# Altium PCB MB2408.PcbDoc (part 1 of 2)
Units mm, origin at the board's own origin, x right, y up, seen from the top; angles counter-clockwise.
Board outline 43 x 47 mm, 2 copper layers (Top Layer, Bottom Layer), stack 0.996 mm thick; 66 components, 54 nets, 306 pads, 690 vias.
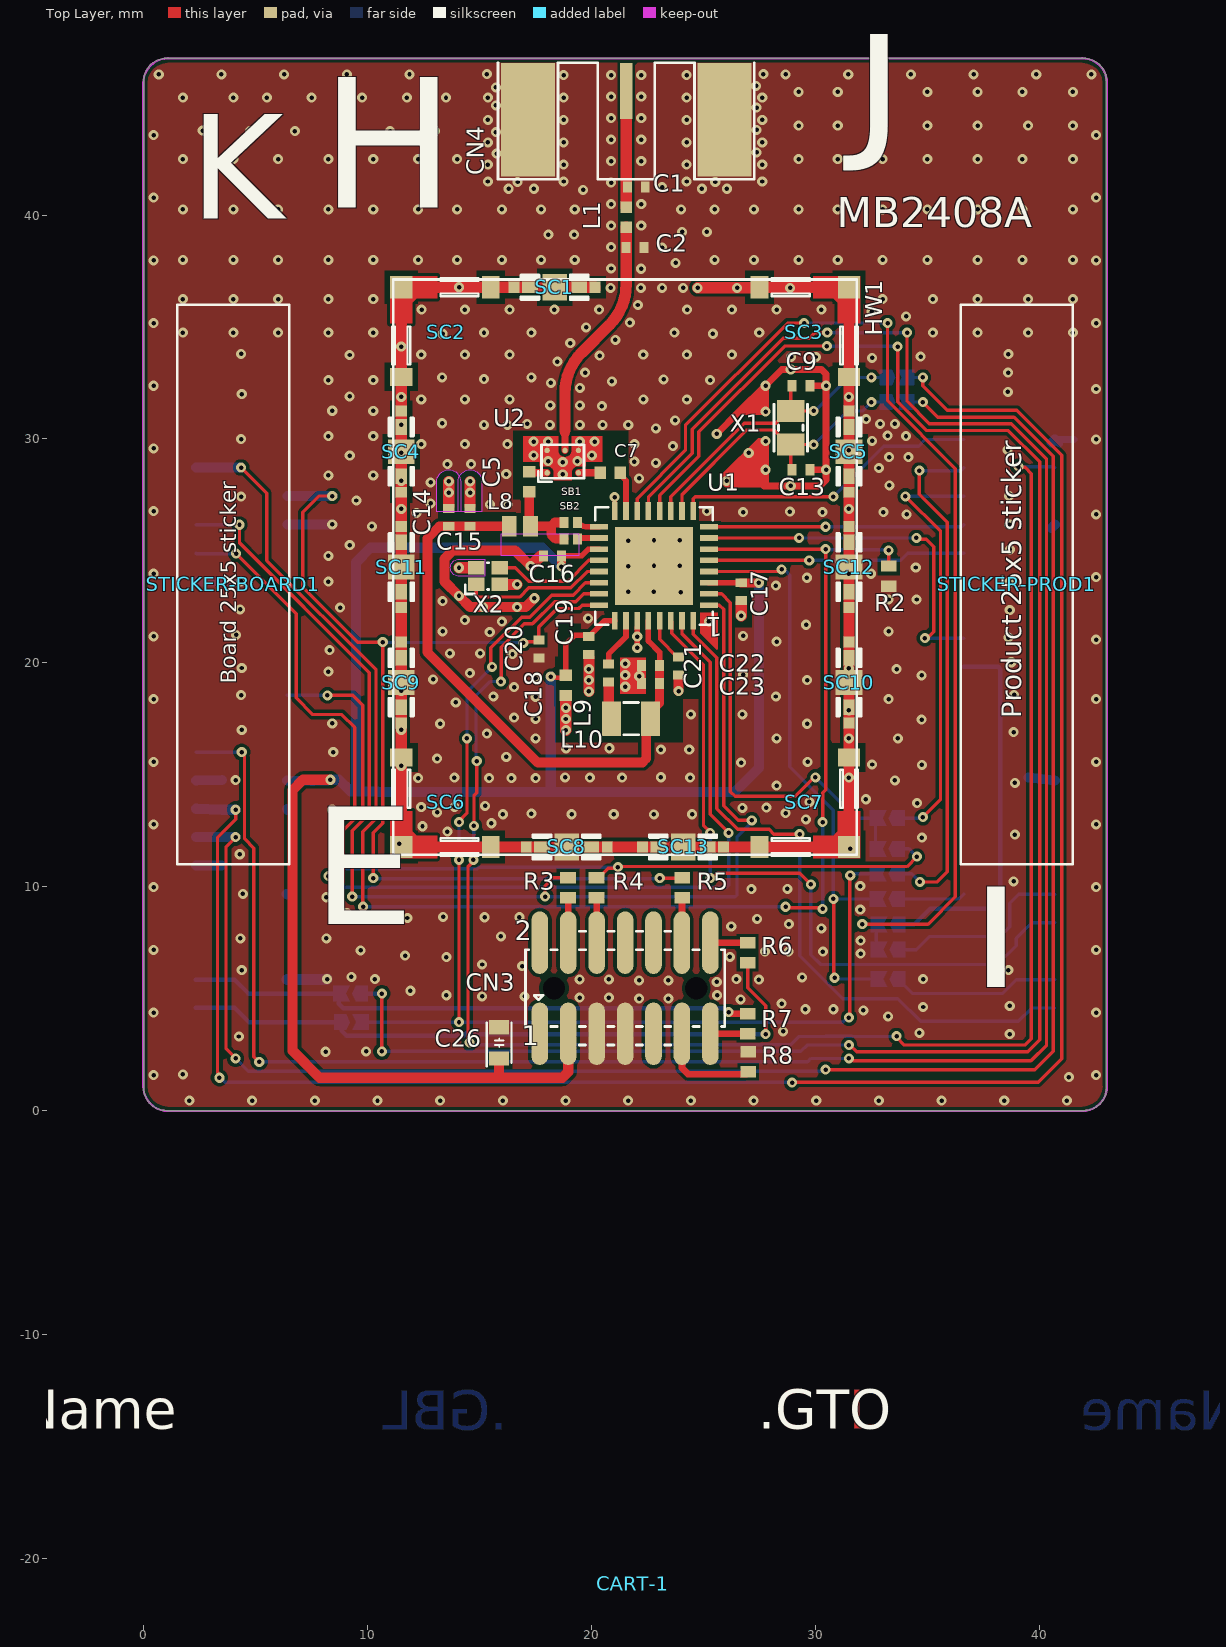
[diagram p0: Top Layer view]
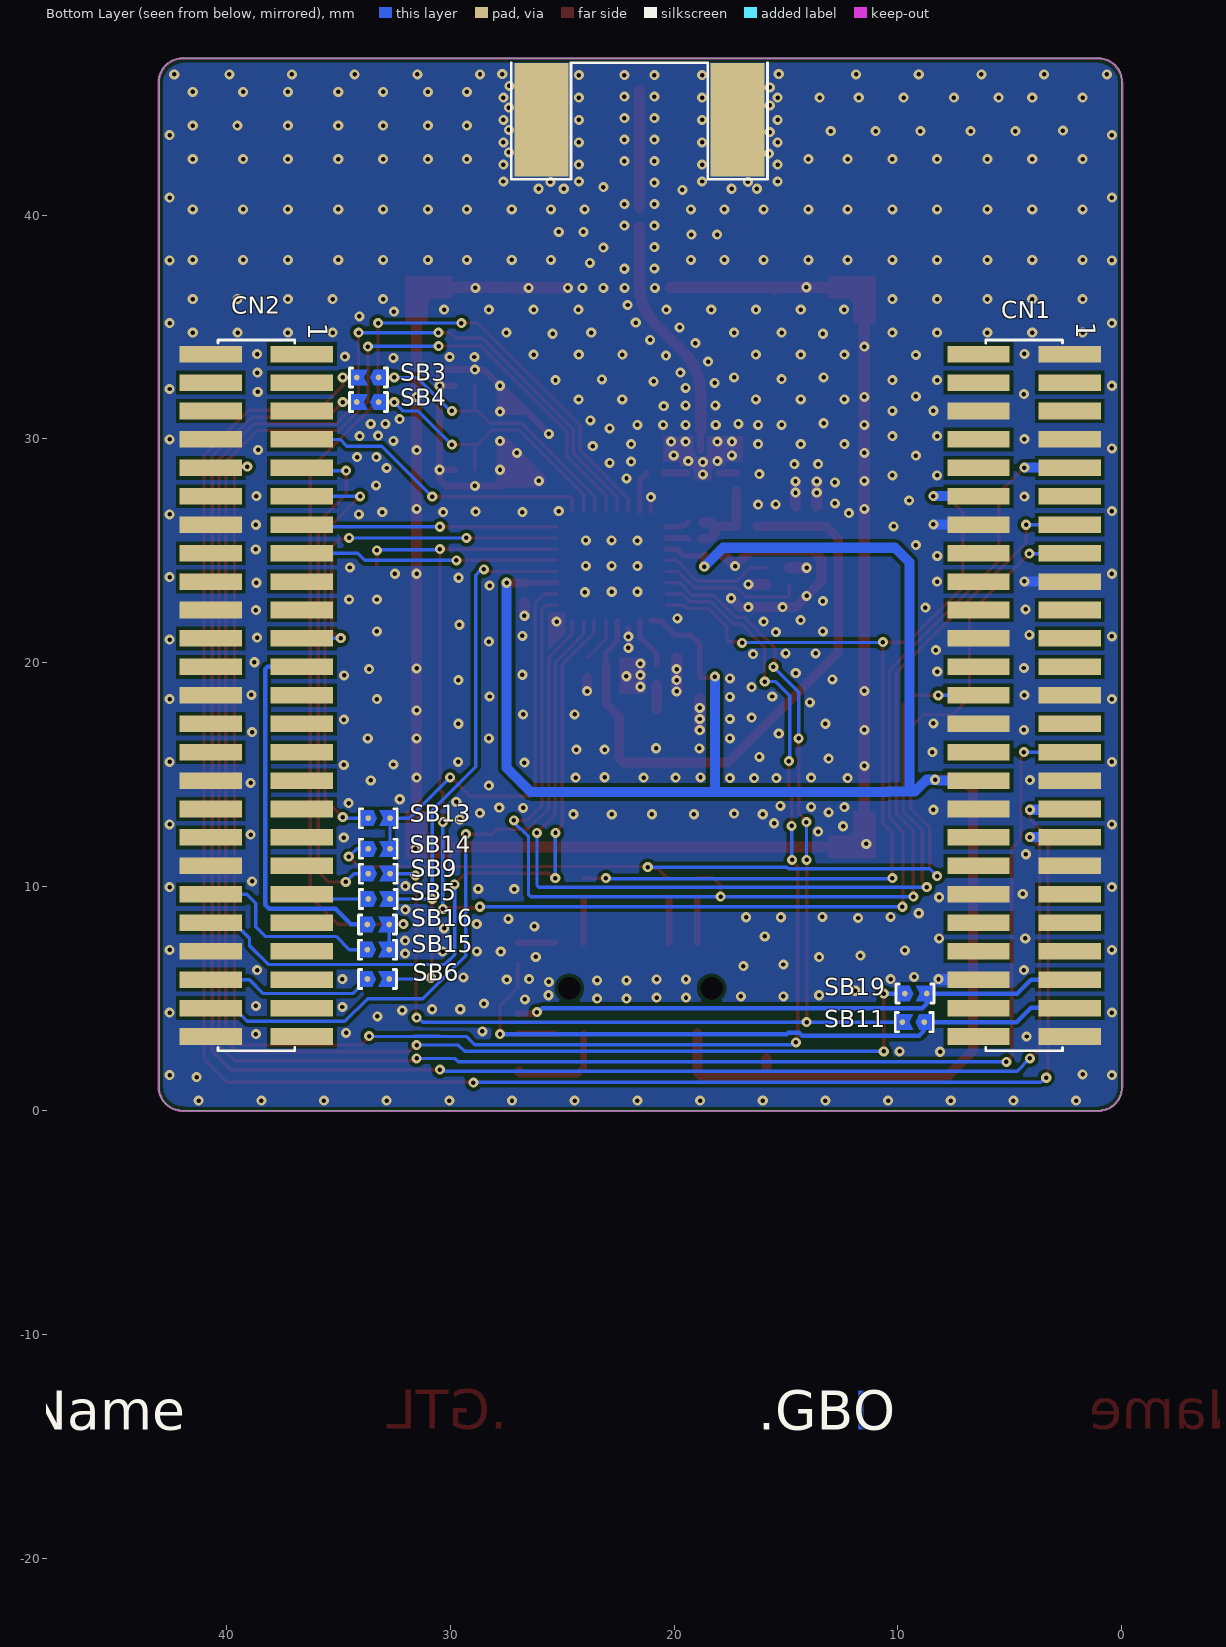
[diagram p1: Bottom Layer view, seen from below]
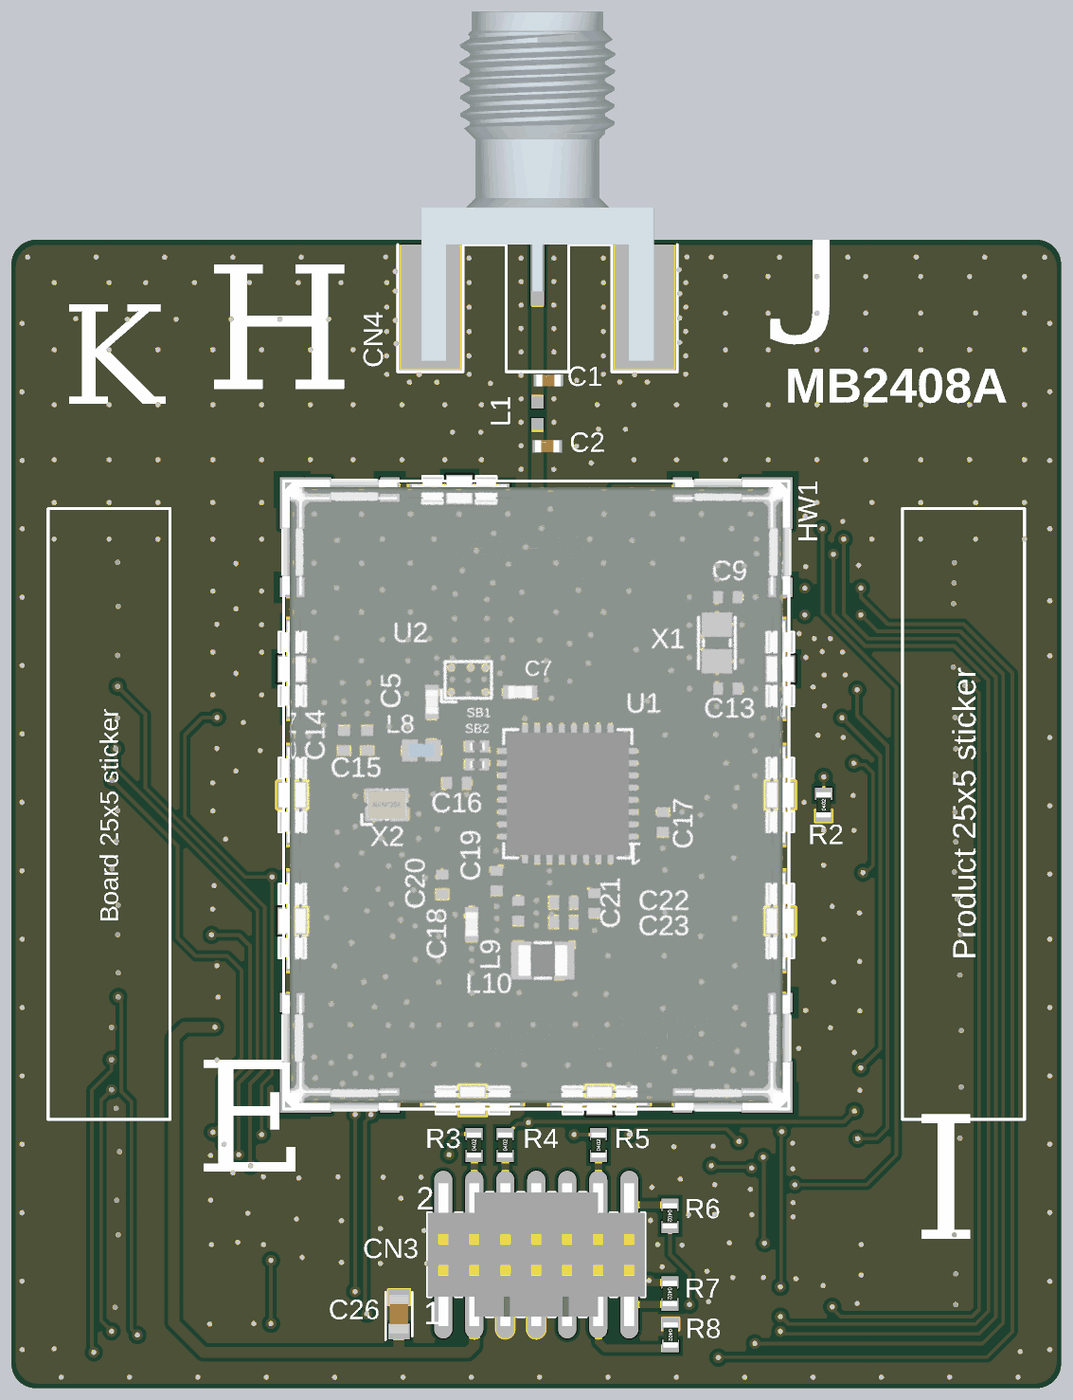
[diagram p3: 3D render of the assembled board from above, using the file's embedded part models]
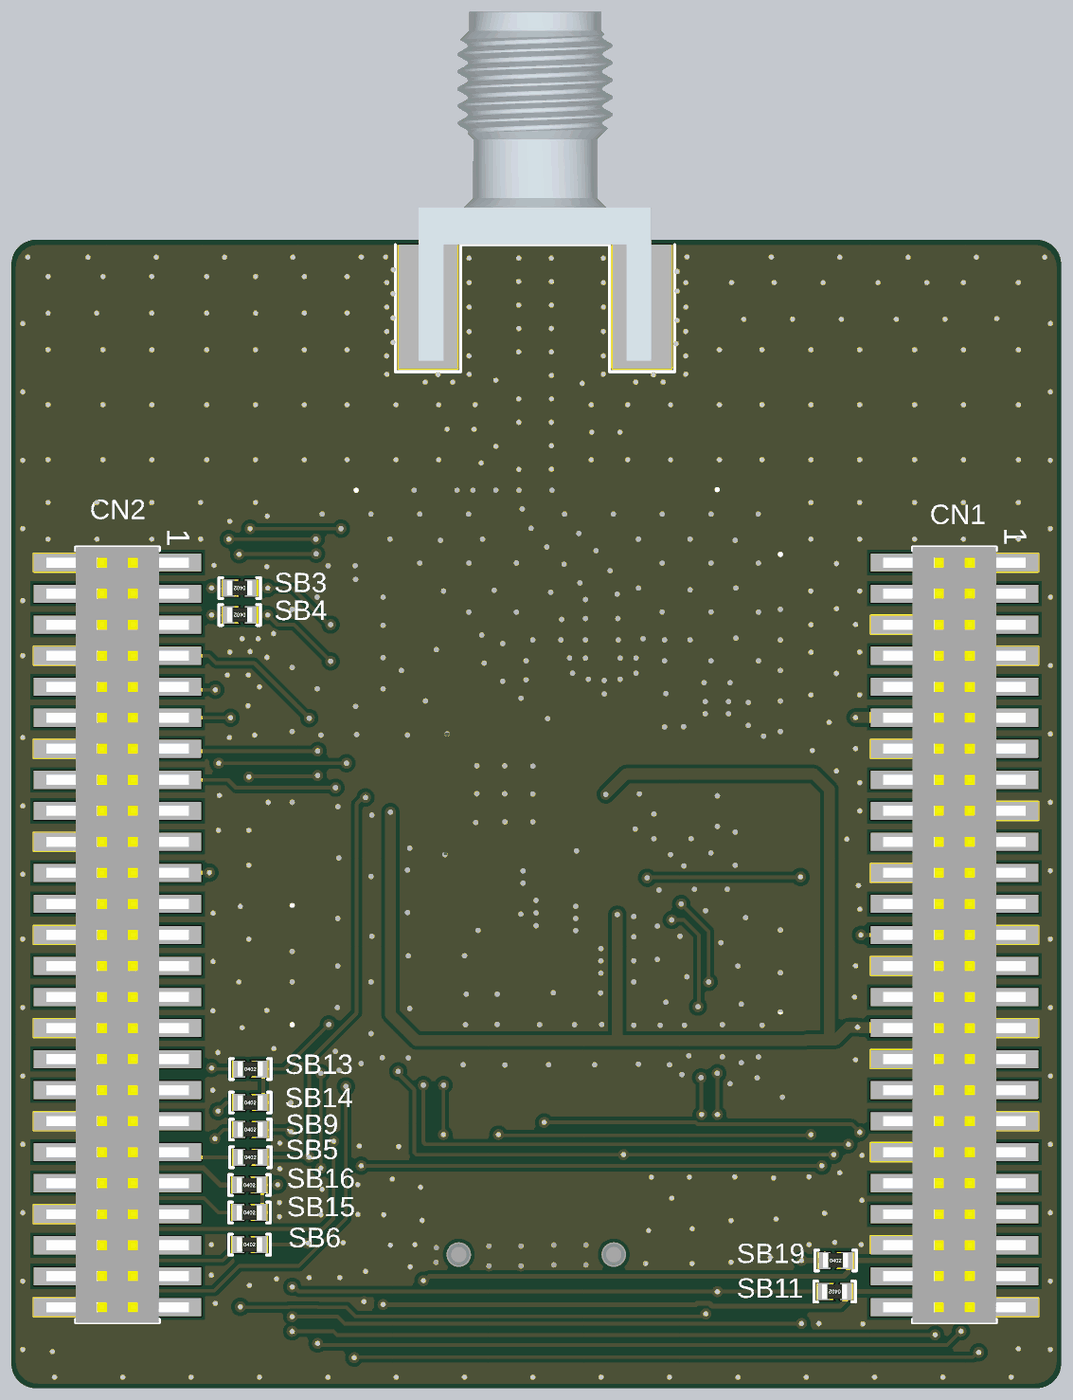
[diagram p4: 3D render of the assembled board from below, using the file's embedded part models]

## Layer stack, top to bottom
Top Solder: solder mask 0.0102, Solder Resist, Dk 3.5
Top Layer: signal copper 0.0406
Dielectric 2: core 0.9144, FR4, Dk 4.3
Bottom Layer: signal copper 0.0406
Bottom Solder: solder mask 0.0102, Solder Resist, Dk 3.5

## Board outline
0,1 ccw(c1,1) 1,0 42,0 ccw(c42,1) 43,1 43,46 ccw(c42,46) 42,47 1,47 ccw(c1,46) 0,46

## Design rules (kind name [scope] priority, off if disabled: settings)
AssemblyTestPointUsage [All] p1 off:
AssemblyTestpoint [All] p1 off: testpointundercomponent=TRUE minsize=1.016 maxsize=2.54 preferedsize=1.524 minholesize=0 maxholesize=1.016 preferedholesize=0.813 testpointgrid=0.025 usegrid=TRUE gridtolerance=0 allowsidetop=TRUE allowsidebottom=TRUE
BoardOutlineClearance [All and not(ObjectKind = 'Component') And (Name = 'CN4')] p1: gap=0.1 ignorepadtopadclearanceinfootprint=FALSE
Clearance [touchesRoom('RoomDefinition_3')] p1: gap=0.095 ignorepadtopadclearanceinfootprint=FALSE
Clearance Clearance_Keepout [All vs IsKeepOut] p2: gap=0.15 ignorepadtopadclearanceinfootprint=TRUE except(0: Poly-Region)
Clearance Clearance_IPD [InPadClass('IPD_PAD')] p3: gap=0.14 ignorepadtopadclearanceinfootprint=FALSE
Clearance Clearance_RF-50R [InNetClass('NC_RF-50R')] p4: gap=0.125 ignorepadtopadclearanceinfootprint=FALSE
Clearance Clearance_Default_Same-net_GND [InNet('GND')] p5: gap=0.15 ignorepadtopadclearanceinfootprint=TRUE except(0: SMDPad-Via SMDPad-Hole Via-Via Via-Region; 0.1: Arc-SMDPad Track-SMDPad Via-Hole; 0.12: SMDPad-SMDPad)
Clearance Clearance_Default [All vs not(ObjectKind = 'Track') And (Net = 'NetC2_2')] p6: gap=0.15 ignorepadtopadclearanceinfootprint=FALSE except(0.1: Arc-Via Track-Via; 0.2: Poly-Region)
ComponentClearance [All] p1 off: gap=0.165 collisioncheckmode=3 verticalgap=0 showdistances=FALSE
ComponentClearance ComponentClearance_CN4 [InComponent('CN4')] p2 off: gap=0.165 collisioncheckmode=3 verticalgap=2540 showdistances=FALSE
DiffPairsRouting [All] p1 off: maxlimit=0.254 minlimit=0.254 mostfreqgap=0.254 toplayer_minwidth=0.381 toplayer_maxwidth=0.381 toplayer_prefwidth=0.381 bottomlayer_minwidth=0.381 bottomlayer_maxwidth=0.381 bottomlayer_prefwidth=0.381 maxuncoupledlength=12.7
FabricationTestPointUsage [All] p1 off: valid=0 allowmultiple=FALSE
FabricationTestpoint [All] p1 off: side=3 testpointundercomponent=TRUE minsize=1.016 maxsize=2.54 preferedsize=1.524 minholesize=0 maxholesize=1.016 preferedholesize=0.813 testpointgrid=0.025 allowsidetop=TRUE allowsidebottom=TRUE usegrid=TRUE gridtolerance=0
FanoutControl Fanout_BGA [IsBGA] p1 off: bgadir=Out bgaviamode=Centered fanoutstyle=Auto fanoutdirection=Alternating viagrid=0.025 // Fanout_BGA (Default Rule)
FanoutControl Fanout_LCC [IsLCC] p2 off: bgadir=Out bgaviamode=Centered fanoutstyle=Auto fanoutdirection=Alternating viagrid=0.025 // Fanout_LCC (Default Rule)
FanoutControl Fanout_SOIC [IsSOIC] p3 off: bgadir=Out bgaviamode=Centered fanoutstyle=Auto fanoutdirection=Alternating viagrid=0.025 // Fanout_SOIC (Default Rule)
FanoutControl Fanout_Small [(CompPinCount < 5)] p4 off: bgadir=Out bgaviamode=Centered fanoutstyle=Auto fanoutdirection=OutThenIn viagrid=0.025 // Fanout_Small (Default Rule)
FanoutControl Fanout_Default [All] p5 off: bgadir=Out bgaviamode=Centered fanoutstyle=Auto fanoutdirection=Alternating viagrid=0.025 // Fanout_Default (Default Rule)
HoleSize [All] p1: absolutevalues=TRUE maxlimit=10 minlimit=0.025 maxpercent=80.000 minpercent=20.000
MinimumSolderMaskSliver [All] p1: minsoldermaskwidth=0.075
PlaneConnect [All] p1: planeconnectstyle=Relief reliefexpansion=0.508 reliefentries=4 reliefconductorwidth=0.21 reliefairgap=0.21
PolygonConnect PolygonConnect_CLIP [TouchesRoom('RoomDefinition')or TouchesRoom('RoomDefinition_1') or   TouchesRoom('RoomDefinition_2')  or TouchesRoom('RoomDefinition_4')  or TouchesRoom('RoomDefinition_5')    or TouchesRoom('RoomDefinition_6')] p1: connectstyle=Direct reliefconductorwidth=0.3 reliefentries=4 polygonreliefangle="90 Angle" airgapwidth=0.25
PolygonConnect PolygonConnect_Default_1 [All] p2: thpad.connectstyle=Direct thpad.reliefconductorwidth=0.3 thpad.reliefentries=4 thpad.polygonreliefangle="90 Angle" thpad.airgapwidth=0.25 smdpad.connectstyle=NoConnect smdpad.reliefconductorwidth=0.254 smdpad.reliefentries=4 smdpad.polygonreliefangle="90 Angle" smdpad.airgapwidth=0.254 via.connectstyle=Direct via.reliefconductorwidth=0.254 via.reliefentries=4 via.polygonreliefangle="90 Angle" via.airgapwidth=0.254
RoomDefinition RoomDefinition_5 [False vs False] p1: confinementstyle=ConfineIn formatcopy=TRUE lockcomponents=FALSE outline 7.053,14.176 7.972,14.176 7.972,12.975 7.053,12.975
RoomDefinition RoomDefinition_4 [False vs False] p2: confinementstyle=ConfineIn formatcopy=TRUE lockcomponents=FALSE outline 16.958,20.887 18.429,20.887 18.429,19.639 16.958,19.639
RoomDefinition RoomDefinition_3 [All] p3: confinementstyle=ConfineIn formatcopy=TRUE lockcomponents=FALSE outline 17.724,29.336 19.774,29.336 19.774,27.744 17.724,27.744
RoomDefinition RoomDefinition_2 [False] p4: confinementstyle=ConfineIn formatcopy=TRUE lockcomponents=FALSE outline 27.072,12.919 27.072,10.495 16.087,10.495 16.087,12.919
RoomDefinition RoomDefinition_1 [False] p5: confinementstyle=ConfineIn formatcopy=TRUE lockcomponents=FALSE outline 32.674,15.775 30.25,15.775 30.25,28.309 32.674,28.309
RoomDefinition [False] p6: confinementstyle=ConfineIn formatcopy=TRUE lockcomponents=FALSE outline 12.674,16.465 10.25,16.465 10.25,27.45 12.674,27.45
RoutingCorners [All] p1 off: cornerstyle=45-Degree minsetback=2.54 maxsetback=2.54
RoutingVias RoutingVias_Default [All] p1: holewidth=0.3 width=0.6 viastyle="Through Hole" minholewidth=0.3 minwidth=0.6 maxholewidth=0.3 maxwidth=0.6 useviatemplates=TRUE viatemplateguid#1={7280008E-C29C-4D1A-93D7-D7784B042BC4} viatemplatename#1=v45h20m0mx0
SilkToSilkClearance [All] p1 off: silktosilkclearance=0.2
SilkToSolderMaskClearance [IsPad] p1 off: minsilkscreentomaskgap=0.2 clearancetoexposedcopper=TRUE
SolderMaskExpansion [All] p1: expansion=0.102 istentingtop=FALSE
UnRoutedNet [All] p1: checkbadconnections=TRUE
ViasUnderSMD [InPadClass('PC__VIAS-IN-PAD')] p1: allowed=TRUE
Width Width_RF-50R [InNetClass('NC_RF-50R')] p1: maxlimit=0.55 minlimit=0.25 preferedwidth=0.51 impedanceprofiledriven=TRUE impedanceprofileid={AD1550EC-3D0E-4E34-9E21-FD44D1EEEC04} impedanceprofilevalue=50.000000 minimp=50.000000 maximp=50.000000 favimp=50.000000
Width Width_Default [All] p2: maxlimit=10 minlimit=0.15 preferedwidth=0.2
12 further rules are at their usual default settings.

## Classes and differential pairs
net class VFBSD: VFBSD
net class VDD: VDD
net class NC_RF-50R: NetC1_2 NetC2_2
component class Designator: C16 C17 C18 C19 C21 C22 C23 C26 CN3 L9 L10 R3 R4 R5 R6 R7 R8
pad class PC__VIAS-IN-PAD: C22-1 C22-2 C23-1 C23-2

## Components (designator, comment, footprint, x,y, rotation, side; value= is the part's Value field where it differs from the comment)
C1 "Capacitor" GRM155--GJM155-0_05-MFG 22,41.25 r180 top value=TBD
C2 "Capacitor" GRM155--GJM155-0_05-MFG 21.95,38.55 r180 top value=TBD
C5 "Capacitor" C0402 17.225,28.088 r270 top value=100pF
C7 "Capacitor" C0402 20.84,28.488 r180 top value=100pF
C9 "Capacitor" C0402_MURATA_GJM-GRM15_H0P5 29.35,32.375 r180 top value=6.8pF
C13 "Capacitor" C0402_MURATA_GJM-GRM15_H0P5 29.35,28.625 r180 top value=6.8pF
C14 "Capacitor" C0402_MURATA_GJM-GRM15_H0P5 13.625,26.5 r270 top value=100pF
C15 "Capacitor" C0402_MURATA_GJM-GRM15_H0P5 14.575,26.5 r270 top value=100nF
C16 "Capacitor" C0402_MURATA_GJM-GRM15_H0P5 18.25,24.776 r0 top value=100nF
C17 "Capacitor" C0402_MURATA_GJM-GRM15_H0P5 26.685,23.175 r90 top value=100nF
C18 "Capacitor" C0402 18.852,18.99 r90 top value=4.7uF
C19 "Capacitor" C0402_MURATA_GJM-GRM15_H0P5 19.875,20.775 r270 top value=330pF
C20 "Capacitor" C0402_MURATA_GJM-GRM15_H0P5 17.65,20.619 r90 top value=100nF
C21 "Capacitor" C0402_MURATA_GJM-GRM15_H0P5 23.883,19.858 r90 top value=220nF
C22 "Capacitor" C0402_MURATA_GJM-GRM15_H0P5 22.633,19.873 r0 top value=4.7uF
C23 "Capacitor" C0402_MURATA_GJM-GRM15_H0P5 22.633,19.077 r0 top value=100nF
C26 "Capacitor" C0603 15.875,3.025 r270 top value=1uF
CART-1 "Comment" Sheetbox_4L2S -23.25,-26.5 r0 top
CN1 "FTSH-125-02-L-DV" CON_SAMTEC_FTSH-125-02-L-DV_INV 4.366,18.548 r270 bottom locked value="Header 25x2"
CN2 "FTSH-125-02-L-DV" CON_SAMTEC_FTSH-125-02-L-DV_INV 38.656,18.548 r270 bottom locked value="Header 25x2"
CN3 "Header 7x2" CON_SAMTEC_FTSH-107-01-L-DV-K-A 21.5,5.465 r0 top locked
CN4 "142-0701-851" 142-0701-851 21.55,44.3 r0 top
HW1 "S02-20150300" SHIELD_HARWIN_S02-25200300_20X25_H3 21.5,24.275 r0 top locked value=S02-25200300R
L1 "Inductor" L0402 21.55,39.9 r90 top value=0R
L8 "Inductor" IND_0402_MURATA_LQW15AN_H0P5 16.8,26.1 r0 top value=56nH
L9 "Inductor" IND_0402_MURATA_LQG15HSXXXX02_H0P5 20.765,19.542 r90 top value=270nH
L10 "Inductor" IND_0805_MURATA_LQM21 21.77,17.505 r180 top value=10uH
R2 "Resistor" R0402 33.275,23.875 r90 top value=100K
R3 "Resistor" R0402 18.95,9.95 r90 top value=47R
R4 "Resistor" R0402 20.225,9.95 r90 top value=47R
R5 "Resistor" R0402 24.05,9.95 r90 top value=47R
R6 "Resistor" R0402 26.975,7.05 r270 top value=47R
R7 "Resistor" R0402 26.975,3.875 r270 top value=47R
R8 "Resistor" R0402 27.003,2.175 r270 top value=47R
SB1 "SB_ON" SOLDER-BRIDGE_R0201_0R 19.075,26.266 r180 top value=0R
SB2 "SB_ON" SOLDER-BRIDGE_R0201_0R 19.075,25.525 r180 top value=0R
SB3 "SB_ON" SOLDER-BRIDGE_R0402-0R 33.65,32.747 r0 bottom
SB4 "SB_ON" SOLDER-BRIDGE_R0402-0R 33.65,31.647 r0 bottom
SB5 "SB_ON" SOLDER-BRIDGE_R0402-0R 33.212,9.452 r180 bottom
SB6 "SB_ON" SOLDER-BRIDGE_R0402-0R 33.246,5.875 r180 bottom
SB9 "SB_ON" SOLDER-BRIDGE_R0402-0R 33.212,10.582 r180 bottom
SB11 "SB_ON" SOLDER-BRIDGE_R0402-0R 9.275,3.95 r0 bottom
SB13 "SB_ON" SOLDER-BRIDGE_R0402-0R 33.212,13.061 r180 bottom
SB14 "SB_ON" SOLDER-BRIDGE_R0402-0R 33.212,11.688 r180 bottom
SB15 "SB_ON" SOLDER-BRIDGE_R0402-0R 33.25,7.187 r180 bottom
SB16 "SB_ON" SOLDER-BRIDGE_R0402-0R 33.25,8.313 r180 bottom
SB19 "SB_ON" SOLDER-BRIDGE_R0402-0R 9.237,5.225 r180 bottom
SC1 "Shield-clip_S0951-46R" CLIP_HARWIN_S0951-46R 18.35,36.775 r180 top value=S0951-46R
SC2 "Shield-clip_S0951-46R" CLIP_HARWIN_S0981-46R 11.5,36.775 r180 top value=S0981-46R
SC3 "Shield-clip_S0951-46R" CLIP_HARWIN_S0981-46R 31.5,36.775 r90 top value=S0981-46R
SC4 "Shield-clip_S0951-46R" CLIP_HARWIN_S0951-46R 11.5,29.433 r90 top value=S0951-46R
SC5 "Shield-clip_S0951-46R" CLIP_HARWIN_S0951-46R 31.5,29.433 r90 top value=S0951-46R
SC6 "Shield-clip_S0951-46R" CLIP_HARWIN_S0981-46R 11.5,11.775 r270 top value=S0981-46R
SC7 "Shield-clip_S0951-46R" CLIP_HARWIN_S0981-46R 31.5,11.775 r0 top value=S0981-46R
SC8 "Shield-clip_S0951-46R" CLIP_HARWIN_S0951-46R 18.89,11.774 r180 top value=S0951-46R
SC9 "Shield-clip_S0951-46R" CLIP_HARWIN_S0951-46R 11.5,19.12 r90 top value=S0951-46R
SC10 "Shield-clip_S0951-46R" CLIP_HARWIN_S0951-46R 31.5,19.12 r270 top value=S0951-46R
SC11 "Shield-clip_S0951-46R" CLIP_HARWIN_S0951-46R 11.5,24.278 r90 top value=S0951-46R
SC12 "Shield-clip_S0951-46R" CLIP_HARWIN_S0951-46R 31.5,24.278 r270 top value=S0951-46R
SC13 "Shield-clip_S0951-46R" CLIP_HARWIN_S0951-46R 24.09,11.775 r0 top value=S0951-46R
STICKER-BOARD1 "Comment" STICKER_BOARD_25X5 4,23.5 r90 top
STICKER-PROD1 "Comment" STICKER_PRODUCT_25X5 39,23.5 r90 top
U1 "IC_STM32WL3R" ICC_VFQFPN32-EPAD_5X5_P050 22.792,24.327 r90 top value=STM32WL3RKBV6
U2 "IC_MLPF-WL-09D3" ICC_CSPG5_1P5X1P9_P060 18.715,28.988 r90 top value=MLPF-WL-09D3
X1 "XTAL_2_PINS" CRY_NX2012SA_2P 28.9,30.5 r90 top value=32.768kHz
X2 "XTAL_4_PINS" CRY_NX1612SA_4P 15.38,23.875 r0 top value=48MHz

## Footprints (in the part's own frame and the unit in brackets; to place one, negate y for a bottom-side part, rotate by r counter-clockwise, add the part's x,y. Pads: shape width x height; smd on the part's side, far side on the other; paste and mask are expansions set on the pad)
142-0701-851 [mm]
  rect 0.55x2.5 smd mask+0.05: 1(0,1.25)
  rect 2.413x5.08 smd mask+0.05: 2(4.381,-0.04) 3(-4.381,-0.04)
  rect 2.413x5.08 smd far side mask+0.05: 4(-4.381,-0.04) 5(4.381,-0.04)
  silkscreen extent -5.72,-2.7 5.72,2.5, body extent -4.8,-2.25 4.8,12.05, height 4.08
C0402 [mm]
  rect 0.51x0.56 smd mask+0.05: 1(-0.45,0) 2(0.45,0)
  body extent -0.5,-0.3 0.5,0.3, height 0.4
C0402_MURATA_GJM-GRM15_H0P5 [mm] "MCD-XXXXX"
  rect 0.4x0.5 smd mask+0.05: 1(-0.4,0) 2(0.4,0)
  body extent -0.53,-0.28 0.53,0.27, height 0.55
C0603 [mm]
  rect 0.64x0.89 smd mask+0.05: 1(-0.7,0) 2(0.7,0)
  silkscreen extent -0.9,-0.55 1.05,0.55, body extent -0.9,-0.5 0.9,0.5, height 1.4
CLIP_HARWIN_S0951-46R [mm] "MCD-01587_CLIP-X1"
  rect 0.48x0.5 smd mask+0.1: 1(-1.81,0) 1(1.81,0)
  rect 0.7x0.5 smd mask+0.1: 1(-1.1,0) 1(1.1,0)
  rect 1.1x1.2 smd mask+0.1: 1(0,0)
  silkscreen extent -1.5,-0.55 1.5,0.55, body extent -2.05,-0.65 2.05,0.65, height 1.28
CLIP_HARWIN_S0981-46R [mm] "MCD-02164"
  rect 0.8x1 smd mask+0.05: 1(-4,0)
  rect 1x0.8 smd mask+0.05: 1(0,4)
  rect 1x1 smd mask+0.05: 1(0,0)
  Top Layer region: -1.6,-0.5 0.5,-0.5 0.5,1.6 -0.5,1.6 -0.5,0.7 -0.7,0.5 -1.6,0.5
  silkscreen extent -3.45,-0.4 0.4,3.45, body extent -4.3,-0.46 0.46,4.3, height 1.4
CON_SAMTEC_FTSH-107-01-L-DV-K-A [mm] "MCD-01959"
  oval 0.74x2.79 smd mask+0.05: 1(-3.81,-2.035) 2(-3.81,2.035) 3(-2.54,-2.035) 4(-2.54,2.035) 5(-1.27,-2.035) 6(-1.27,2.035) 7(0,-2.035) 8(0,2.035) 9(1.27,-2.035) 10(1.27,2.035) 11(2.54,-2.035) 12(2.54,2.035) 13(3.81,-2.035) 14(3.81,2.035)
  round 0 hole 1 unplated paste-2539.97 mask+0.05: NPTH1(-3.175,0) NPTH2(3.175,0)
  silkscreen extent -4.44,-2.54 4.44,2.54, body extent -4.44,-2.92 4.45,2.92, height 6.12
CON_SAMTEC_FTSH-125-02-L-DV_INV [mm]
  rect 0.74x2.79 smd mask+0.05: 1(-15.24,2.035) 2(-15.24,-2.035) 3(-13.97,2.035) 4(-13.97,-2.035) 5(-12.7,2.035) 6(-12.7,-2.035) 7(-11.43,2.035) 8(-11.43,-2.035) 9(-10.16,2.035) 10(-10.16,-2.035) 11(-8.89,2.035) 12(-8.89,-2.035) 13(-7.62,2.035) 14(-7.62,-2.035) 15(-6.35,2.035) 16(-6.35,-2.035) 17(-5.08,2.035) 18(-5.08,-2.035) 19(-3.81,2.035) 20(-3.81,-2.035) 21(-2.54,2.035) 22(-2.54,-2.035) 23(-1.27,2.035) 24(-1.27,-2.035) 25(0,2.035) 26(0,-2.035) 27(1.27,2.035) 28(1.27,-2.035) 29(2.54,2.035) 30(2.54,-2.035) 31(3.81,2.035) 32(3.81,-2.035) 33(5.08,2.035) 34(5.08,-2.035) 35(6.35,2.035) 36(6.35,-2.035) 37(7.62,2.035) 38(7.62,-2.035) 39(8.89,2.035) 40(8.89,-2.035) 41(10.16,2.035) 42(10.16,-2.035) 43(11.43,2.035) 44(11.43,-2.035) 45(12.7,2.035) 46(12.7,-2.035) 47(13.97,2.035) 48(13.97,-2.035) 49(15.24,2.035) 50(15.24,-2.035)
  silkscreen extent -15.88,-1.71 15.88,1.71, body extent -15.87,-2.92 15.88,2.92, height 4.82
CRY_NX1612SA_4P [mm] "MCD-02262"
  rect 0.75x0.6 smd mask+0.038: 1(-0.525,-0.375) 2(0.525,-0.375) 3(0.525,0.375) 4(-0.525,0.375)
  silkscreen extent -1.02,-0.8 0.03,0.6, body extent -0.8,-0.6 0.8,0.6, height 0.31
CRY_NX2012SA_2P [mm]
  rect 1x1.25 smd mask+0.05: 1(-0.75,0) 2(0.75,0)
  silkscreen extent -1.05,-0.75 1.05,0.75, body extent -1.05,-0.63 1.05,0.63, height 0.6
GRM155--GJM155-0_05-MFG [mm]
  rect 0.4x0.5 smd paste+0 mask+0: 1(-0.4,0) 2(0.4,0)
  body extent -0.7,-0.38 0.7,0.38, height 0.25
ICC_CSPG5_1P5X1P9_P060 [mm]
  round 0.24 smd mask+0.05: A1(-0.5,0.7) A3(-0.5,-0.7) B1(0.5,0.7) B2(0.5,-0.1) B3(0.5,-0.7)
  silkscreen extent -0.9,-0.95 0.75,1.1, body extent -0.75,-0.95 0.75,0.95, height 0.69
ICC_VFQFPN32-EPAD_5X5_P050 [mm]
  rect 0.25x0.8 smd mask+0.05: 1(-1.75,-2.45) 2(-1.25,-2.45) 3(-0.75,-2.45) 4(-0.25,-2.45) 5(0.25,-2.45) 6(0.75,-2.45) 7(1.25,-2.45) 8(1.75,-2.45) 17(1.75,2.45) 18(1.25,2.45) 19(0.75,2.45) 20(0.25,2.45) 21(-0.25,2.45) 22(-0.75,2.45) 23(-1.25,2.45) 24(-1.75,2.45)
  rect 0.8x0.25 smd mask+0.05: 9(2.45,-1.75) 10(2.45,-1.25) 11(2.45,-0.75) 12(2.45,-0.25) 13(2.45,0.25) 14(2.45,0.75) 15(2.45,1.25) 16(2.45,1.75) 25(-2.45,1.75) 26(-2.45,1.25) 27(-2.45,0.75) 28(-2.45,0.25) 29(-2.45,-0.25) 30(-2.45,-0.75) 31(-2.45,-1.25) 32(-2.45,-1.75)
  rect 3.5x3.5 smd mask+0.05: 33(0,0)
  silkscreen extent -2.63,-2.63 2.63,2.63, body extent -2.5,-2.5 2.5,2.5, height 0.9
IND_0402_MURATA_LQG15HSXXXX02_H0P5 [mm] "MCD-03474"
  rect 0.4x0.5 smd mask+0.05: 1(-0.4,0) 2(0.4,0)
  body extent -0.55,-0.28 0.55,0.28, height 0.55
IND_0402_MURATA_LQW15AN_H0P5 [mm] "MCD-01606"
  rect 0.65x0.9 smd mask+0.05: 1(-0.475,0) 2(0.475,0)
  body extent -0.55,-0.35 0.55,0.35, height 0.6
IND_0805_MURATA_LQM21 [mm]
  rect 0.85x1.55 smd mask+0.05: 1(-0.875,0) 2(0.875,0)
  silkscreen extent -0.33,-0.72 0.33,0.72, body extent -1.1,-0.72 1.1,0.72, height 1.45
L0402 [mm]
  rect 0.51x0.51 smd mask+0.05: 1(-0.45,0) 2(0.45,0)
  body extent -0.5,-0.3 0.5,0.3, height 0.51
R0402 [mm]
  rect 0.51x0.7 smd mask+0.05: 1(-0.45,0) 2(0.45,0)
  body extent -0.52,-0.3 0.52,0.3, height 0.4
Sheetbox_4L2S [mil] "Sheetbox 4 layers / 2 silkscreens"
  round 20 on Mech16: 1(813.78,210.69) 1(2736.9,210.69)
SHIELD_HARWIN_S02-25200300_20X25_H3 [mm] "MCD-03503"
  silkscreen extent -10.35,-12.85 10.35,12.85, body extent -10.1,-12.6 10.1,12.6, height 3.2
SOLDER-BRIDGE_R0201_0R [mm] "MCD-03219"
  rect 0.4x0.5 smd mask+0.05: 1(-0.3,0) 2(0.3,0)
  body extent -0.32,-0.17 0.32,0.17, height 0.26
SOLDER-BRIDGE_R0402-0R [mil] "MCD-01619"
  round 10 smd paste-393.7: 1(-17.72,0) 2(20.67,0)
  Top Layer region: 1.48,13.78 8.37,0 1.48,-13.78 30.51,-13.78 30.51,13.78
  Top Layer region: -30.51,-13.78 -30.51,13.78 -8.86,13.78 -2.95,0 -8.86,-13.78
  silkscreen extent -33,-17 33,17, body extent -20,-12 20,12, height 14
STICKER_BOARD_25X5 [mm] "Sticker to mention board reference + serial number"
  silkscreen extent -12.5,-2.5 12.5,2.5
STICKER_PRODUCT_25X5 [mm] "Sticker to mention board CPN code"
  silkscreen extent -12.5,-2.5 12.5,2.5

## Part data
C1: library part MCD-01600, "Capacitor, MLCC", Manufacturer=MURATA, Manufacturer_Part_Number=TBD, Package=0402
C2: library part MCD-01600, "Capacitor, MLCC,", Manufacturer=MURATA, Manufacturer_Part_Number=TBD, Package=0402
C5 C7 C14: library part MCD-03446, "Capacitor, MLCC, 100pF, 50V, C0G/NP0, +/-1%, 0402, T=0.5mm", Manufacturer=MURATA, Manufacturer_Part_Number=GCM1555C1H101FA16, Package=0402
C9 C13: library part MCD-03452, "Capacitor, MLCC, 6.8pF, 50V,C0G/NP0, +/-0.05pF, 0402, T=0.5mm", Manufacturer=MURATA, Manufacturer_Part_Number=GJM1555C1H6R8WB01, Package=0402
C15 C16 C17 C23: library part MCD-03442, "Capacitor, MLCC, 100nF, 25V, X7R, +/-10%, 0402, T=0.5mm", Manufacturer=MURATA, Manufacturer_Part_Number=GRM155R71E104KE14, Package=0402
C18 C22: library part MCD-03431, "Capacitor, MLCC, 4.7uF, 10V, X5R, +/-20%, 0402, T=0.5mm", Manufacturer=MURATA, Manufacturer_Part_Number=GRM155R61A475MEAA, Package=0402
C19: library part MCD-04785, "Capacitor, MLCC, 330pF, 50V, C0G, 5%, 0402, T=0.5mm", Manufacturer=MURATA, Manufacturer_Part_Number=GCM1555C1H331JA16, Package=0402
C20: library part MCD-00006, "Capacitor, MLCC, 100nF, 16V, X7R, +/-10%, 0402, T=0.5mm", Manufacturer=YAGEO, Manufacturer_Part_Number=CC0402KRX7R7BB104, Package=0402
C21: library part MCD-03077, "Capacitor, MLCC, 220nF, 35V, X6S, +/-10%, 0402, T=0.5mm", Manufacturer=MURATA, Manufacturer_Part_Number=GRM155C8YA224KE01, Package=0402
C26: library part MCD-00010, "Capacitor, MLCC, 1uF, 16V, X5R, 10%, 0603, T=0,8mm", Manufacturer=YAGEO, Manufacturer_Part_Number=CC0603KRX5R7BB105, Package=0603
CART-1: library part MCD-00279
CN1 CN2: library part MCD-02746, "Header, 25x2, 12.7mm, VR, SMD, T=4.83mm", Manufacturer=SAMTEC
CN3: library part MCD-01531, "Header, 7x2, 1.27mm, VR, T=5.97mm, FTSH series STDC14 without Alignment Pin", Manufacturer=SAMTEC, Manufacturer_Part_Number=FTSH-107-01-L-DV-K
HW1: library part MCD-03503, "RFI shield CAN, 25x20x3mm", Manufacturer=HARWIN, Manufacturer_Part_Number=S02-25200300R, Package=25x20x3mm
L1: library part MCD-01937, "Resistor, 0R, 0402, +/-5%, 1/16W", Manufacturer=YAGEO, Manufacturer_Part_Number=RC0402JR-070RL, Package=0402
L8: library part MCD-02074, "Inductor, 56nH, +/-0.2nH, Itemp=200mA max, 1R17, 0402, T=0.6mm, Qmin=25", Manufacturer=MURATA, Manufacturer_Part_Number=LQW15AN56NG00, Package=0402
L9: library part MCD-03470, "Inductor, 270nH, +/-2%, 110mA, 4R94, 0402, T=0.5mm", Manufacturer=MURATA, Manufacturer_Part_Number=LQG15HSR27G02, Package=0402
L10: library part MCD-02317, "Inductor, 10uH, +/-20%, 0A1, 0R5, 0805, T=1.45mm", Manufacturer=MURATA, Manufacturer_Part_Number=LQM21FN100M80L, Package=0805
R2: library part MCD-00059, "Resistor, 100K, 0402, +/-1%, 1/16W", Manufacturer=YAGEO, Manufacturer_Part_Number=RC0402FR-07100KL, Package=0402
R3 R4 R5 R6 R7 R8: library part MCD-00481, "Resistor,47R,0402,1%,1/16W", Manufacturer=YAGEO, Manufacturer_Part_Number=RC0402FR-0747RL, Package=R0402
SB1 SB2: library part MCD-03219, "Resistor, 0R, 0201, Solder Bridge ON , 1/20W,", Manufacturer=YAGEO, Manufacturer_Part_Number=RC0201JR-070RL, Package=SB0201
SB3 SB4 SB5 SB6 SB9 SB11 SB13 SB14 SB15 SB16 SB19: library part MCD-01618, "Solder Bridge 0402 ON", Manufacturer=YAGEO, Manufacturer_Part_Number=RC0402JR-070RL, Package=SB0402
SC1 SC4 SC5 SC8: library part MCD-01587, "shield clip Harwin S0951-46R to fix RF shielded cavity", Manufacturer=HARWIN, Manufacturer_Part_Number=S0951-46R, Package=1.1x3.9mm
SC2 SC3 SC6 SC7: library part MCD-02164, "shield clip Harwin S0981-46R to fix RF shielded cavity - SMT RFI Shield Clip, Corner (T+R)", Manufacturer=HARWIN, Manufacturer_Part_Number=S0981-46R, Package=1.1x3.9mm
SC9 SC10 SC11 SC12 SC13: library part MCD-01587, "RFI shield clip mini TIN SMD", Manufacturer=HARWIN, Manufacturer_Part_Number=S0951-46R, Package=1.1x3.9mm
U1: library part MCD-04431, "MCU, ARM Cortex-M0 32-bit, 128KB Flash, 16KB SRAM, With Crypto", Manufacturer=STMICROELECTRONICS, Manufacturer_Part_Number=STM32WL3RKBV6, Package=QFN32
U2: library part MCD-05120, "IC, 315MHz low pass filter matched to WBA mini board", Manufacturer=STMICROELECTRONICS, Manufacturer_Part_Number=MLPF-WL-09D3, Package=CSPG5
X1: library part MCD-01445, "Crystal, 32.768kHz, 7pF, +/-20ppm, 80K, 2.05x1.2mm", Manufacturer=NDK, Manufacturer_Part_Number=NX2012SA-32.768KHZ-EXS00A-MU00389, Package=2.05x1.2mm
X2: library part MCD-03559, "Crystal, 48MHz, 8pF, +/-10 ppm, 22R, 1.6x1.2mm", Manufacturer=NDK, Manufacturer_Part_Number="NX1612SA-48.000 MHz-EXS00A-CS12140", Package=1.6*1.2mm

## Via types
v1: diameter 0.45, hole 0.2, Top Layer to Bottom Layer, tented both sides, 690 vias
